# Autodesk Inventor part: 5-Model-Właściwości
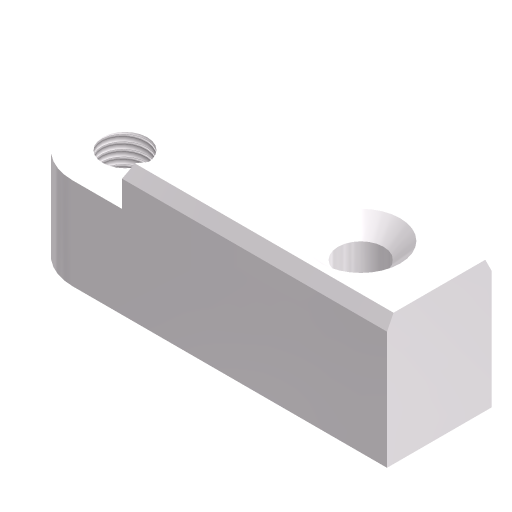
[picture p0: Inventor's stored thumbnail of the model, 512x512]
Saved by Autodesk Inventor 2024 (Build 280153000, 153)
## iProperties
Company: ATC
Shininess: 21.0
Length Units: 11269
Angle Units: 11279
Time Units: 11290
Mass Units: 11283
Compacted: True
Created: 2023-03
Part Number: 5-Model-Właściwości
Document SubType Name: Modeling
Designer: Andrzej Jaskulski
Material: Kurs-AJ
Checked By: A.J.
Engr Approved By: Andrzej Jaskulski
Description: Ćwiczenia iProperties
Mfg Approved By: Andrzej Jaskulski
Density: 1 g/cm^3
Appearance: Kurs-AJ
Authority: A.J.
Density: 0.0
Volumn: 0.0
Area: 0.0
PropertySet Name: Model Information
Control State: 0
Master: False
Checked Out: False
Wys: 50 mm
FiOtw: 17 mm
Hgwintu: 42 mm
Ha: 50 mm
Title: A.J.: Kurs R2024-MEP
Author: Andrzej Jaskulski
Comments: Ćwiczenia w zarządzaniu Właściwościami.
Revision Number: 1/24
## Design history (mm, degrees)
sketch "Podstawa"
  geometry: L1 (0, 0)-(140, 0); L2 (140, 0)-(140, 40); L3 (140, 40)-(0, 40); L4 (0, 40)-(0, 0)
  constraints: 8 end point, 2 parallel, 1 horizontal, 1 perpendicular, 1 other
  dimensions: "L1" = 140 distance of L1.start L1.end; "L2" = 40 distance of L1.end L2.end
extrude "Baza" new body sketch "Podstawa" taper "d1" = 0 deg; distance "Ha" = 50
hole "Otwór W" diameter "d18" = 17; stored, may be unused: drill point angle "d10" = 118 deg, countersink angle "d22" = 90 deg; dims "d7" = 55, "d16" = 20, "d17" = 30, "Hgwintu" = 42, "Hotworu" = 45, "Hpoglebienia" = 15
hole "Otwór St" diameter "d11" = 17.4; stored, may be unused: countersink angle "d13" = 90 deg, drill point angle "d51" = 118 deg; dims "d12" = 30, "d14" = 20 (= 0.5 x L2), "d46" = 6, "d48" = 2, "d50" = 8, "R1" = 30
node "Bryła1"
node "Korpusy bryłowe"
node "Korpusy powierzchniowe"
node "Początek"
fillet "Zaokrąglenie" dims "d3" = 20
chamfer "Faza" distance "d4" = 2.5; stored, may be unused: second distance "d5" = 5, angle "d15" = 45 deg
node "Płaszczyzna YZ"
node "Płaszczyzna XZ"
node "Płaszczyzna XY"
node "Oś X"
node "Oś Y"
node "Oś Z"
node "Punkt  środkowy"
other parameters: "d2" = 90 deg, "Wys" = 50 (= Ha) [user parameter], "FiOtw" = 17.4 (= d11) [user parameter]
